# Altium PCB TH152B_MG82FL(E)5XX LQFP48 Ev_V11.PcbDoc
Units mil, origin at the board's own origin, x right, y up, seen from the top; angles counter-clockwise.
Board outline 2850 x 2110 mil, 2 copper layers (Top Layer, Bottom Layer); 49 components, 67 nets, 298 pads, 95 vias.
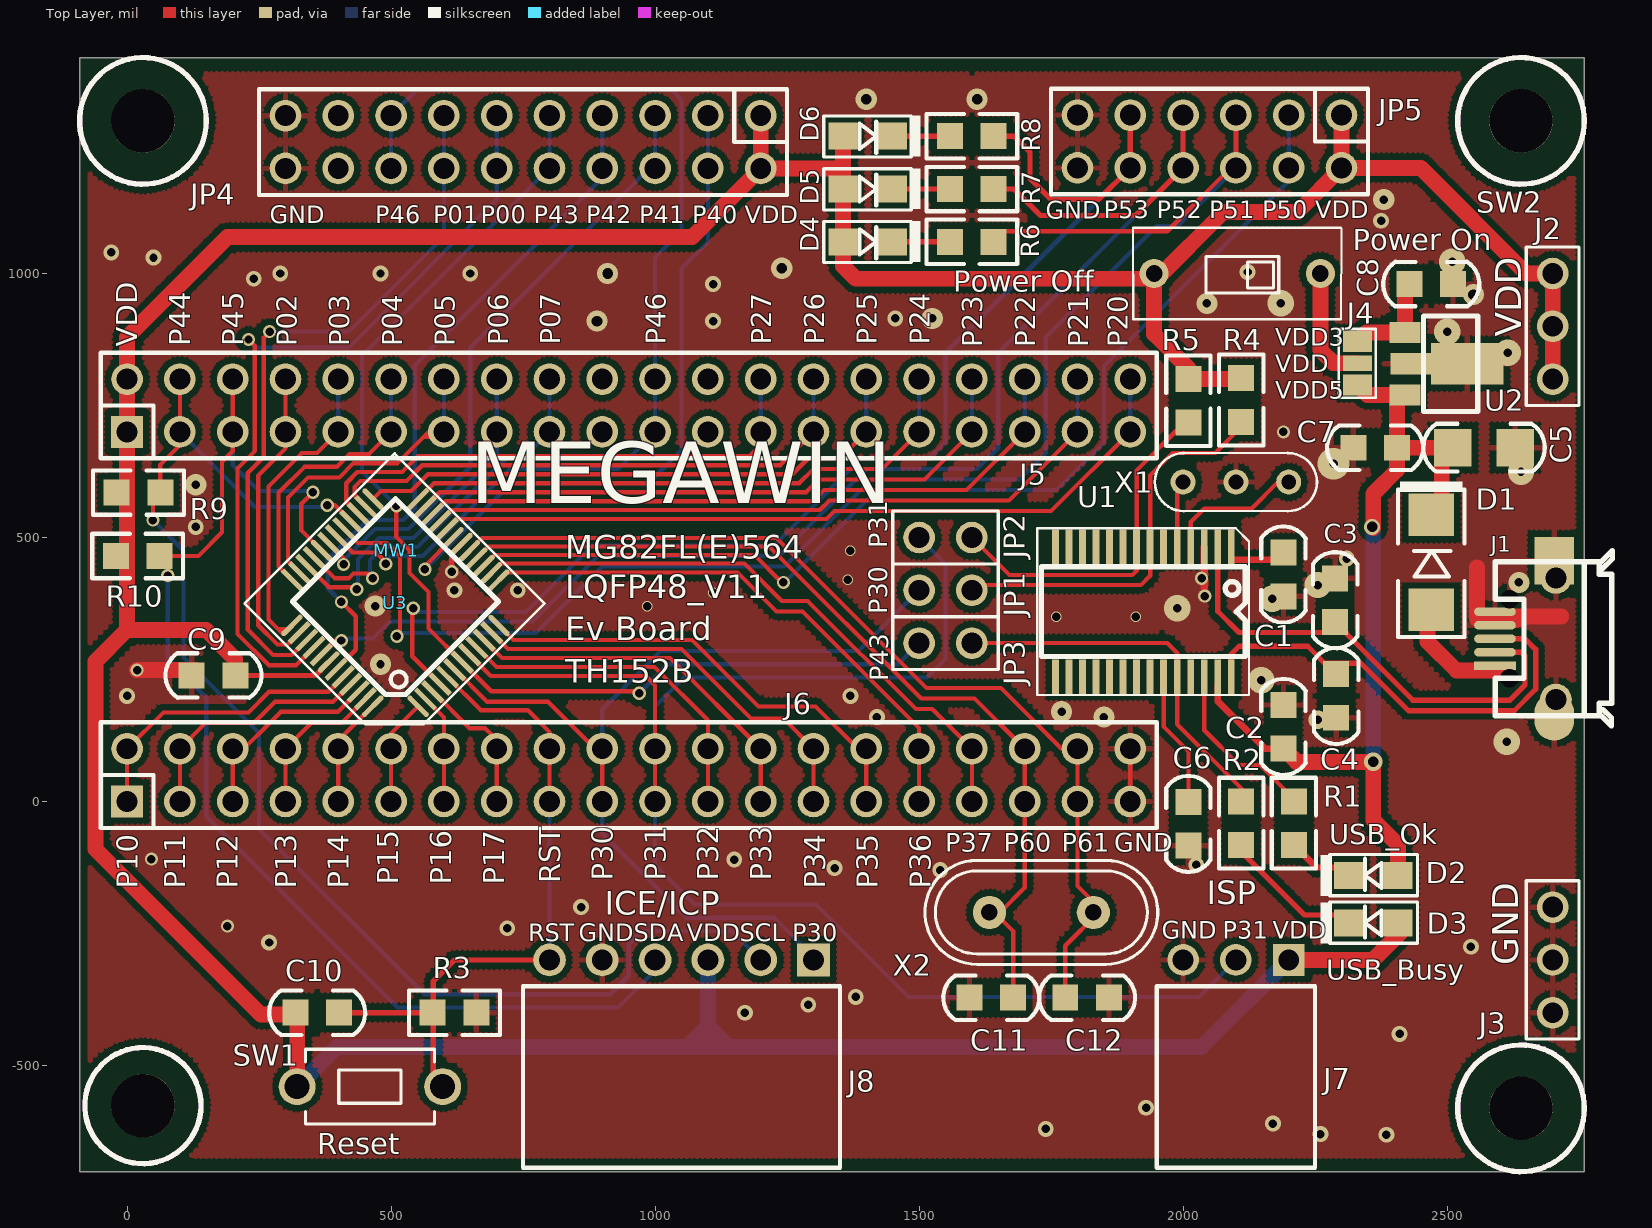
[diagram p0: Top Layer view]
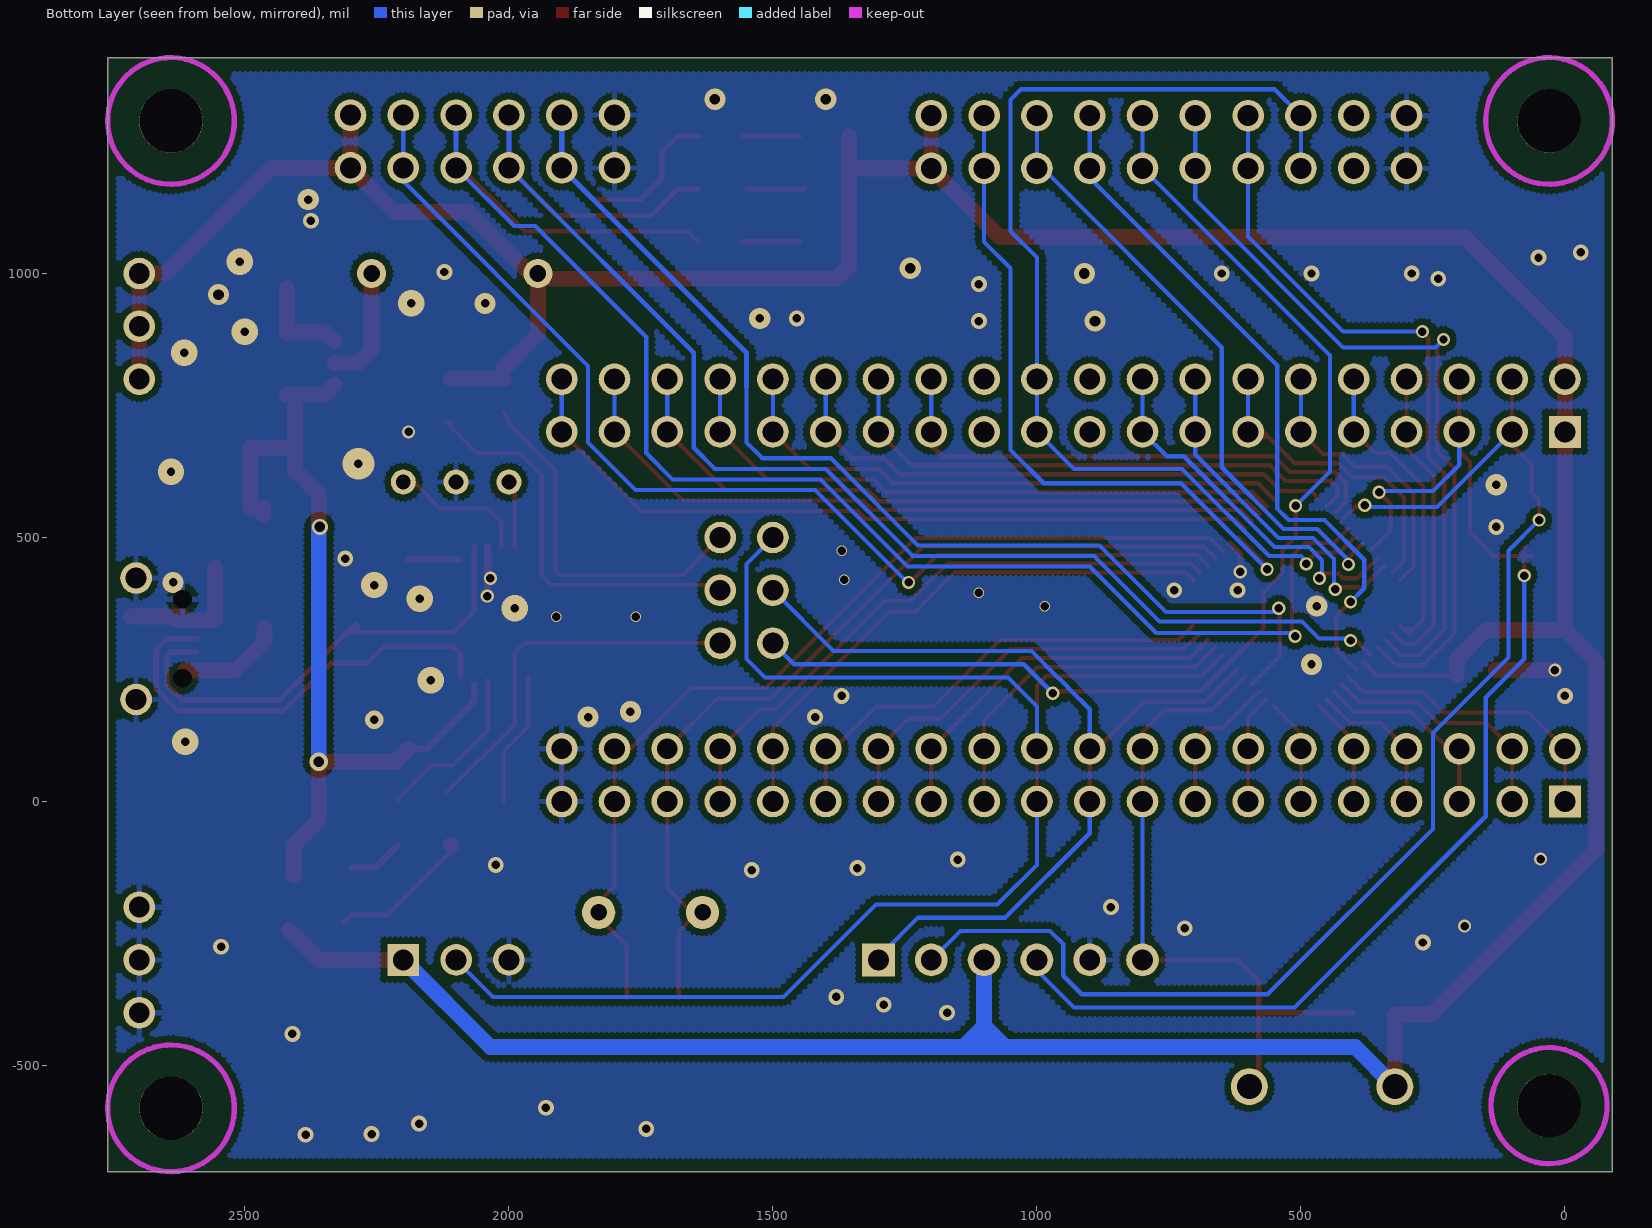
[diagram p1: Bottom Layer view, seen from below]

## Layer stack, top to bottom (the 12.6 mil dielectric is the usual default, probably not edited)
Top Layer: signal copper 1.4
Dielectric: dielectric 12.6, FR-4, Dk 4.8
Bottom Layer: signal copper 1.4

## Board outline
-90,-701 -90,1409 2760,1409 2760,-701

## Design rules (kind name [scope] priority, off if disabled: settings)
Clearance 12 [All] p1 off: gap=12
Clearance 10 [All] p2 off: gap=10
Clearance 6 [All] p3: gap=6
ComponentClearance [All] p1 off: gap=10 collisioncheckmode=3 verticalgap=10 showdistances=FALSE
HoleSize [All] p1: absolutevalues=TRUE maxlimit=500 minlimit=1 maxpercent=80.000 minpercent=20.000
MinimumSolderMaskSliver [All] p1 off: minsoldermaskwidth=10
PolygonConnect VIA [ISVIA] p1: connectstyle=Direct reliefconductorwidth=10 reliefentries=4 polygonreliefangle="90 Angle"
PolygonConnect [All] p2: connectstyle=Relief reliefconductorwidth=10 reliefentries=4 polygonreliefangle="90 Angle"
RoomDefinition "TH152B_MG82FL(E)5XX LQFP48 Ev_V10" [InComponentClass('TH152B_MG82FL(E)5XX LQFP48 Ev_V10')] p1: confinementstyle=ConfineIn formatcopy=TRUE lockcomponents=FALSE outline -685,-1335 3285,-1335 3285,1895 -685,1895
RoutingVias [All] p1: holewidth=16 width=25 viastyle="Through Hole" minholewidth=16 minwidth=24 maxholewidth=28 maxwidth=50
SilkToSilkClearance [All] p1 off: silktosilkclearance=10
SilkscreenOverComponentPads [All] p1 off: minsilkscreentomaskgap=10
SolderMaskExpansion [All] p1 off: expansion=4
Width [All] p1: maxlimit=200 minlimit=6 preferedwidth=10
23 further rules are at their usual default settings.

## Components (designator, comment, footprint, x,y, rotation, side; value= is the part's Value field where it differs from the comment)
C1 "4.7uF" 0805C 2190,430 r270 top
C2 "0.1uF" 0805C 2190,141.34 r270 top
C3 "15pF" 0805C 2288,381.34 r90 top
C4 "15pF" 0805C 2290,200 r270 top
C5 "4.7uF" 1206C 2570,670 r0 top
C6 "0.1uF" 0805C 2010,-42.34 r90 top
C7 "0.1uF" 0805C 2363.66,670 r180 top
C8 "4.7uF" 0805C 2470,980 r0 top
C9 "0.1uF" 0805C 163.66,238.85 r180 top
C10 "1u" 0805C 360,-400 r0 top
C11 "NC" 0805C 1636.81,-371.58 r180 top
C12 "NC" 0805C 1818.15,-371.58 r0 top
D1 "1N5817" D5817_SMD_1 2470,453 r270 top
D2 "Yellow" 0805D 2360,-140 r180 top
D3 "RED" 0805D 2360,-230 r180 top
D4 "Green" 0805D 1403.08,1060 r0 top
D5 "RED" 0805D 1403.08,1160 r0 top
D6 "Green" 0805D 1403.08,1260 r0 top
J1 "Micro USB母座" JACK_USB_SMD290X220P065 2590.71,308.28 r180 top
J2 "*" PS3P254 2700,800 r90 top
J3 "*" PS3P254 2700,-200 r270 top
J4 "*" JUMP3_SMD 2330,830 r90 top
J5 "*" PS20X2P254 0,700 r0 top locked
J6 "*" PS20X2P254 0,0 r0 top locked
J7 "*" PS3P254f_90 2200,-300 r180 top
J8 "*" PS6P254F_90 1300,-300 r180 top
JP1 "JUMPER2" PS2P254 1500,400 r0 top
JP2 "JUMPER2" PS2P254 1500,500 r0 top
JP3 "JUMPER2" PS2P254 1500,300 r0 top
JP4 "*" PS10X2P254 1200,1299 r180 top
JP5 "*" PS6X2P254 2300,1300 r180 top
MW1 "MW-A4" MEGAWIN_T 510,476 r0 top
R1 "1K" 0805R 2210,-41 r270 top
R2 "1K" 0805R 2110,-41 r270 top
R3 "47K" 0805R 620,-400 r180 top
R4 "4.7K" 0805R 2110,760.34 r270 top
R5 "4.7K" 0805R 2010,759 r270 top
R6 "1K" 0805R 1600,1060 r180 top
R7 "1K" 0805R 1600,1160 r180 top
R8 "1K" 0805R 1600,1260 r180 top
R9 "4.7K" 0805R 21.66,585 r180 top
R10 "4.7K" 0805R 20,465 r180 top
SW1 "SW TACT-SPST" SW_T_2P 460,-540 r0 top
SW2 "-" DIP2_SW 2260,1000 r180 top
U1 "MA101_TSSOP28" TSSOP28_170P065 1924.84,359.52 r180 top locked
U2 "AIC1734-33(SOT-89)" SOT89 2420,829.06 r270 top
U3 "MG82Fx564_LQFP48" LQFP48_7X7_050 551.24,180.26 r45 top locked (schematic designator U1)
X1 "6MHz" X3P 2200,605 r180 top
X2 "NC" X49U 1731.57,-210 r0 top

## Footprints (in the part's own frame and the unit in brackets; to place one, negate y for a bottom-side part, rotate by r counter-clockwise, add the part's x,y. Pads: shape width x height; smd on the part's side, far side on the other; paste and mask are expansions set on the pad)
0805C [mm]
  rect 1.25x1.25 smd: 1(-1.05,0) 2(1.05,0)
  silkscreen extent -2.31,-1.07 2.31,1.07
0805D [mm]
  rect 1.4x1.3 smd: 1(-1.192,0) 2(1.192,0)
  silkscreen extent -2.12,-1 2.53,0.98
0805R [mm]
  rect 1.25x1.25 smd: 1(-1.05,0) 2(1.05,0)
  silkscreen extent -2.18,-1.07 2.18,1.07
1206C [mm]
  rect 1.8x1.8 smd: 1(-1.5,0) 2(1.5,0)
  silkscreen extent -2.92,-1.15 2.92,1.16
D5817_SMD_1 [mil]
  rect 80x86.61 smd: 1(90,0) 2(-90,0)
  silkscreen extent -153,-63 142,63
DIP2_SW [mm]
  round 1.4 hole 0.8: 1(0,0) 2(8,0)
  silkscreen extent -1.02,-2.2 9.02,2.2
JACK_USB_SMD290X220P065 [mm]
  rect 1.9x1.8 on Mech2: 0(-2.85,-1.15) 0(-2.85,1.15)
  round 0.8 hole 0.9 unplated: 1(-0.7,1.9) 5(-0.7,-1.9)
  rect 2x0.4 smd: 1(0,1.3)
  oval 2x0.4 smd: 2(0,0.65) 3(0,0) 4(0,-0.65) 5(0,-1.3)
  round 1.524 hole 1: 5(-2.931,2.921) 5(-2.931,-2.921)
  oval 1.9x2.3 smd: 5(-2.85,3.75)
  rect 1.9x2.3 smd: 5(-2.85,-3.75)
  silkscreen extent -5.65,-4.25 -0.01,4.2
JUMP3_SMD [mil]
  rect 40x55 smd: 1(-41,0) 3(41,0)
  rect 30x55 smd: 2(0,0)
  silkscreen extent -65,-35 65,35
LQFP48_7X7_050 [mm]
  oval 0.254x1.35 smd: 1(0,0) 12(5.5,0) 25(5.513,8.585) 32(2.013,8.585)
  rect 0.254x1.35 smd: 2(0.5,0) 3(1,0) 4(1.5,0) 5(2,0) 6(2.5,0) 7(3,0) 8(3.5,0) 9(4,0) 10(4.5,0) 11(5,0) 26(5.013,8.585) 27(4.513,8.585) 28(4.013,8.585) 29(3.513,8.585) 30(3.013,8.585) 31(2.513,8.585) 33(1.513,8.585) 34(1.013,8.585) 35(0.513,8.585) 36(0.013,8.585)
  oval 1.35x0.254 smd: 13(7.036,1.549) 14(7.036,2.049) 15(7.036,2.549) 16(7.036,3.049) 17(7.036,3.549) 18(7.036,4.049) 19(6.921,4.549) 37(-1.536,7.049) 42(-1.536,4.549) 48(-1.536,1.549)
  rect 1.35x0.254 smd: 20(7.036,5.049) 21(7.036,5.549) 22(7.036,6.049) 23(7.036,6.549) 24(7.036,7.049) 38(-1.536,6.549) 39(-1.536,6.049) 40(-1.536,5.549) 41(-1.536,5.049) 43(-1.536,4.049) 44(-1.536,3.549) 45(-1.536,3.049) 46(-1.536,2.549) 47(-1.536,2.049)
  silkscreen extent -2.4,-0.8 7.8,9.4
MEGAWIN_T [mil]
PS2P254 [mil]
  round 60 hole 39.37: 1(0,0) 2(100,0)
  silkscreen extent -50,-50 150,50
PS3P254 [mil]
  round 60 hole 39.37: 1(0,0) 2(100,0) 3(200,0)
  silkscreen extent -50,-50 250,50
PS3P254f_90 [mil]
  rect 60x60 hole 39.37: 1(0,0)
  round 60 hole 39.37: 2(100,0) 3(200,0)
  silkscreen extent -50,50 250,394
PS6P254F_90 [mil]
  rect 62x62 hole 39.37: 1(0,0)
  round 62 hole 39.37: 2(100,0) 3(200,0) 4(300,0) 5(400,0) 6(500,0)
  silkscreen extent -50,50 550,394
PS6X2P254 [mil]
  round 60 hole 39.37: 1(0,0) 2(0,100) 3(100,0) 4(100,100) 5(200,0) 6(200,100) 7(300,0) 8(300,100) 9(400,0) 10(400,100) 11(500,0) 12(500,100)
  silkscreen extent -50,-50 550,150
PS10X2P254 [mil]
  round 60 hole 39.37: 1(0,0) 2(0,100) 3(100,0) 4(100,100) 5(200,0) 6(200,100) 7(300,0) 8(300,100) 9(400,0) 10(400,100) 11(500,0) 12(500,100) 13(600,0) 14(600,100) 15(700,0) 16(700,100) 17(800,0) 18(800,100) 19(900,0) 20(900,100)
  silkscreen extent -50,-50 950,150
PS20X2P254 [mil]
  rect 60x60 hole 39.37: 1(0,0)
  round 60 hole 39.37: 2(0,100) 3(100,0) 4(100,100) 5(200,0) 6(200,100) 7(300,0) 8(300,100) 9(400,0) 10(400,100) 11(500,0) 12(500,100) 13(600,0) 14(600,100) 15(700,0) 16(700,100) 17(800,0) 18(800,100) 19(900,0) 20(900,100) 21(1000,0) 22(1000,100) 23(1100,0) 24(1100,100) 25(1200,0) 26(1200,100) 27(1300,0) 28(1300,100) 29(1400,0) 30(1400,100) 31(1500,0) 32(1500,100) 33(1600,0) 34(1600,100) 35(1700,0) 36(1700,100) 37(1800,0) 38(1800,100) 39(1900,0) 40(1900,100)
  silkscreen extent -50,-50 1950,150
SOT89 [mm]
  rect 1.016x1.5 smd: 1(-1.5,0) 3(1.5,0)
  rect 2x3.5 smd: 2(0,3)
  rect 1.016x2.6 smd: 2(0,0.6)
  silkscreen extent -2.3,0.9 2.3,3.5
SW_T_2P [mil]
  round 70 hole 47.24: 1(-137.79,0) 2(137.79,0)
  silkscreen extent -122,-71 122,71
TSSOP28_170P065 [mil]
  rect 13x65 smd: 1(-166.34,-123) 2(-140.75,-123) 3(-115.16,-123) 4(-89.57,-123) 5(-63.98,-123) 6(-38.39,-123) 7(-12.79,-123) 8(12.8,-123) 9(38.39,-123) 10(63.98,-123) 11(89.57,-123) 12(115.16,-123) 13(140.75,-123) 14(166.34,-123) 15(166.34,123) 16(140.75,123) 17(115.16,123) 18(89.57,123) 19(63.98,123) 20(38.39,123) 21(12.8,123) 22(-12.79,123) 23(-38.39,123) 24(-63.98,123) 25(-89.57,123) 26(-115.16,123) 27(-140.75,123) 28(-166.34,123)
  silkscreen extent -200,-158 201,158
X3P [mm]
  round 1.2 hole 0.711: 1(0,0) 2(5.08,0) 3(2.54,0)
  silkscreen extent -1.36,-1.4 6.44,1.4
X49U [mm]
  round 1.6 hole 0.8: 1(-2.5,0) 2(2.5,0)
  silkscreen extent -5.6,-2.5 5.6,2.5

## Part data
C1 C5 C8: library part CAP
C2 C3 C4 C6 C7 C9: library part "CAP NP"
C10: library part C
C11 C12: library part "C NP"
D1: library part DIODE_ZD, "Schottky Diode"
D2 D3 D4 D5 D6: library part LED
J1: library part CON5, "Connector"
J2 J3 J4 J7: library part CON3
J5 J6: library part CON40A
J8: library part CON6
JP4: library part CON10X2
JP5: library part CON6X2
R1 R2 R4 R5 R6 R7 R8: library part R_Dup1
R3 R9 R10: library part R
SW2: library part SW-2
U2: library part AIC1734-33(SOT-89)_0
X1: library part CRYSTAL_RC
X2: library part CRYSTAL

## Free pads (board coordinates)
  round 120 hole 120 unplated: 0(30,-576) 0(30,1289) 0(2640,-581) 0(2640,1289)

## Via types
v1: diameter 30, hole 16, Top Layer to Bottom Layer, tented both sides, 35 vias
v2: diameter 25, hole 16, Top Layer to Bottom Layer, tented both sides, 25 vias
v3: diameter 50, hole 16, Top Layer to Bottom Layer, tented both sides, 10 vias
v4: diameter 40, hole 16, Top Layer to Bottom Layer, tented both sides, 9 vias
v5: diameter 20, hole 16, Top Layer to Bottom Layer, tented both sides, 6 vias
v6: diameter 40, hole 20, Top Layer to Bottom Layer, tented both sides, 6 vias
v7: diameter 35, hole 16, Top Layer to Bottom Layer, tented both sides, 1 vias
v8: diameter 30, hole 20, Top Layer to Bottom Layer, tented both sides, 1 vias
v9: diameter 35, hole 20, Top Layer to Bottom Layer, tented both sides, 1 vias
v10: diameter 60, hole 16, Top Layer to Bottom Layer, tented both sides, 1 vias

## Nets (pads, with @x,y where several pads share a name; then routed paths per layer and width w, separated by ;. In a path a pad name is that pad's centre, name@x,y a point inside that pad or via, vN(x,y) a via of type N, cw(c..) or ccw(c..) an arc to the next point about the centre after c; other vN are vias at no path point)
D+: C4.1 J1.3 U1.28 | length 853.6
  Top Layer w10: U1.28 2091.18,279.18 2106,294 2236,294 2268.16,261.84 2336.88,261.84 2426.72,172 2627.16,172 2667.71,212.55 2667.71,288.2 2647.64,308.28 J1.3
D-: C3.1 J1.2 U1.2 | length 933.5
  Top Layer w10: U1.2 2065.59,360.41 2106,320 C3.1@2288,320 ; C3.1@2288,335 C3.1@2288,320 ; C3.1@2296,331 C3.1@2307,320 ; C3.1@2309,320 C3.1@2307,320 ; J1.2 2641.14,282.69 2647.71,276.12 2647.71,220.84 2618.87,192 2435,192 C3.1@2307,320 ; C3.1@2288,320 C3.1@2307,320
GND_POWER: C1.2 C2.1 C3.2 C4.2 C5.2 C6.1 C7.2 C8.2 C9.2 C11.2 C12.2 J1.4 J1.5 J3.1 J3.2 J3.3 J6.39 J6.40 J7.3 J8.5 JP4.19 JP4.20 JP5.11 JP5.12 R3.1 U1.3 U2.2 U3.18 X1.3 | length 616
  Top Layer w8: J6.39 J6.40
  Top Layer w10: v2(615,435) 615,469.44 U3.18
  Top Layer w15: 2040,406 v2@2040,416 ; U1.3 v2@2040,416 ; v2@2041,415 v2@2040,416
  Top Layer w30: v2(19,248.85) C9.2@131,248.85 ; 2556.57,345.91 2556.57,443 ; 2560,343.32 2630,343.32 ; 2619.25,350.32 2716.34,350.32
  other v1: 2385,-631 2260,-630 1740,-620 2170,-610 1930,-580 2410,-440 1170,-400 1290,-385 1380,-370 2545,-275 269,-267 720,-240 860,-200 1540,-130 1340,-126 2025,-120 1150,-110 1420,160 0,200 1370,200 620,400 740,400 2310,460 130,520 1110,910 1455,915 1110,980 240,990 290,1000 480,1000 650,1000 2122.21,1002.83 50,1030 -30,1040 2375,1100
  other v2: 190,-236 46,-109 2041,389 2035,423 2190,700
  other v3: 2612.91,113 2148,230 1989,366 2169,384 2255,410 2640,624.9 2615,850 2500,890 2185,943.39 2510,1022
  other v4: 1850,160 1770,170 480,260 470,370 2636,415 130,600 1525,915 2045,943.39 2380,1140
  other v5: 1760,350 1910,350 985,370 1110,395 1365,420 1370,475
  other v6: 890,910 2550,960 910,1000 1240,1010 1400,1330 1610,1330
  other v7: 2255,155
  other v10: 2285,640
MA101_RX: JP2.2 R5.2 U1.8 | length 686.1
  Top Layer w8: JP2.2 1671.15,428.85 1903.85,428.85 1912.05,437.05 U1.8 1912.05,627.05 2001.33,716.33 2001.33,726.33 2010,735 R5.2@2010,737.66
MA101_TX: JP1.2 R4.2 U1.7 | length 755
  Top Layer w8: JP1.2@1610,410 1920,410 1937.64,427.64 1937.64,617.64 1980.12,660.12 2060.78,660.12 2110,709.34 R4.2 R4.2@2120,719
NetC1_1: C1.1 U1.1 | length 95.8
  Top Layer w13: U1.1@2094.2,458 C1.1@2190,458
NetC6_2: C6.2 U1.23 | length 306.3
  Top Layer w8: 1963.23,191.18 1963.23,141.77 ; U1.23 1963.23,141.77 ; C6.2 2010,95 1963.23,141.77
NetD1_1: D1.1 J1.1 | length 199.7
  Top Layer w30: D1.1@2463,330 2463,302.91 2517.91,248 J1.1@2612.91,248
NetD2_2: D2.2 R1.2 | length 105.7
  Top Layer w12: R1.2 2252.66,-125 D2.2@2298.08,-125
NetD3_2: D3.2 R2.2 | length 273
  Top Layer w10: R2.2 2110,-95 2230,-215 2298.08,-215 D3.2
  Top Layer w30: R2.2@2108.66,-82.34 R2.2
NetD4_2: D4.2 R6.2 | length 108.7
  Top Layer w10: D4.2 R6.2
NetD5_2: D5.2 R7.2 | length 108.7
  Top Layer w10: D5.2@1441.34,1160 D5.2 R7.2@1550,1160
NetD6_2: D6.2 R8.2 | length 108.7
  Top Layer w10: D6.2 R8.2
NetJ4_2: J4.2 SW2.1 | length 225.4
  Top Layer w30: SW2.1 2260,855 2285,830 J4.2
NetU1_4: U1.4 X1.1 | length 263.8
  Top Layer w8: U1.4 2014.41,529.41 2040,555 2130,555 2180,605 X1.1
NetU1_5: U1.5 X1.2 | length 127.1
  Top Layer w8: U1.5 1988.82,593.82 X1.2
P00: JP4.11 JP4.12 U3.40 | length 1511.1
  Top Layer w8: v2(230,875) 242,863 242,663.85 208.95,630.79 208.95,317.55 268.54,257.96 320.01,257.96 U3.40
  Bottom Layer w8: v2(230,875) 245,860 420,860 700,1140 JP4.12 JP4.11
P01: JP4.13 JP4.14 U3.39 | length 1472.1
  Top Layer w8: 259,864 259,750 ; v2(270,890) 259,879 259,750 ; U3.39 311.85,277.64 276.69,277.64 228.63,325.71 228.63,622.48 259,652.85 259,750
  Bottom Layer w8: v2(270,890) 420,890 600,1070 JP4.14 JP4.13
P02: J5.7 J5.8 U3.38 | length 564.8
  Top Layer w8: J5.7 300,668.85 248.32,617.16 248.32,333.86 284.85,297.33 303.7,297.33 U3.38 ; J5.7@300,725 J5.8
P03: J5.9 J5.10 U3.37 | length 607.6
  Top Layer w8: U3.37@303.7,326.85 285.71,326.85 ; U3.37 295.54,317.01 285.71,326.85 ; J5.9 359.84,659.84 330.99,659.84 268,596.85 268,344.56 285.71,326.85
  Bottom Layer w8: J5.9 J5.10
P04: J5.11 J5.12 U3.36 | length 536.6
  Top Layer w8: U3.36 287,445.21 287,584.85 336,633.85 397,633.85 421,657.85 457.85,657.85 J5.11
  Bottom Layer w8: J5.11 J5.12
P05: J5.13 J5.14 U3.35 | length 638.2
  Top Layer w8: U3.35 305,455.04 305,575.85 343,613.85 402,613.85 429,640.85 512,640.85 571.15,700 J5.13 ; 563.44,690.85 J5.13@604,690.85
  Bottom Layer w8: J5.13 J5.14
P06: J5.15 J5.16 U3.34 | length 663.2
  Top Layer w8: U3.34 381.88,406 431,406 v2(435,402)
  Bottom Layer w8: v2@437.23,397.23 437.23,459.23 477,499 542.21,499 700,656.79 J5.15 J5.16
P07: J5.17 J5.18 U3.33 | length 708.6
  Top Layer w8: U3.33 392.72,423 420,423 429,432 456,432 v2(465,423)
  Bottom Layer w8: v2@460,423 460,457 484.85,481.85 550,481.85 722,653.85 753.85,653.85 J5.17 J5.18
P10: J6.1 J6.2 U3.44 | length 566.1
  Top Layer w8: J6.1 J6.2 68.85,168.85 230,168.85 269,207.85 381.25,207.85 U3.44
P11: J6.3 J6.4 U3.45 | length 474.3
  Top Layer w8: J6.3 J6.4 148.85,148.85 240,148.85 280,188.85 390.09,188.85 U3.45
P12: J6.5 J6.6 U3.46 | length 370.1
  Top Layer w8: J6.5 200,78.85 291,169.85 398.93,169.85 U3.46
P13: J6.7 J6.8 U3.47 | length 290.6
  Top Layer w8: J6.7 J6.8 348.85,148.85 405.77,148.85 U3.47
P14: J6.9 J6.10 U3.48 | length 192.4
  Top Layer w8: J6.9 J6.10 ; J6.10@400,115.24 U3.48
P15: J6.11 J6.12 U3.1 | length 201.5
  Top Layer w8: J6.11 J6.12 500,129.01 U3.1
P16: J6.13 J6.14 U3.2 | length 208.6
  Top Layer w8: U3.2 600,159.34 J6.14 J6.13
P17: J6.15 J6.16 U3.3 | length 246
  Top Layer w8: U3.3 648.33,138.85 678,138.85 J6.16@691,125.85 ; J6.15 J6.16
P20: J5.39 J5.40 U3.20 | length 1469.4
  Top Layer w8: U3.20 624.73,534.85 1324.85,534.85 1340,550 1750,550 J5.39
  Bottom Layer w8: J5.39 J5.40
P21: J5.37 J5.38 U3.21 | length 1377.5
  Top Layer w8: U3.21 613.9,551.85 1311.85,551.85 1330,570 1670,570 J5.37
  Bottom Layer w8: J5.37 J5.38
P22: J5.35 J5.36 U3.22 | length 1285.7
  Top Layer w8: U3.22 603.06,568.85 1298.85,568.85 1320,590 1590,590 J5.35
  Bottom Layer w8: J5.35 J5.36
P23: J5.33 J5.34 U3.23 | length 1193.8
  Top Layer w8: U3.23 592.22,585.85 1285.85,585.85 1310,610 1510,610 J5.33
  Bottom Layer w8: J5.33 J5.34
P24: J5.31 J5.32 U3.24 | length 1102
  Top Layer w8: U3.24 581.38,602.85 1272.85,602.85 1300,630 1430,630 J5.31
  Bottom Layer w8: J5.31 J5.32
P25: J5.29 J5.30 U3.25 | length 1087
  Top Layer w8: U3.25 480.86,587.85 538.15,587.85 570.15,619.85 1259.85,619.85 1290,650 1350,650 J5.29
  Bottom Layer w8: J5.29 J5.30
P26: J5.27 J5.28 U3.26 | length 1057.8
  Top Layer w8: U3.26 431,579.59 431,595.85 442,606.85 529,606.85 559,636.85 1236.85,636.85 J5.27
  Bottom Layer w8: J5.27 J5.28
P27: J5.25 J5.26 U3.27 | length 1002.2
  Top Layer w8: U3.27 415,567.75 415,602.85 436,623.85 521,623.85 551,653.85 1022,653.85 ; 1042,653.85 1022,653.85 ; J5.25@1200,674.7 1179.15,653.85 1022,653.85
  Bottom Layer w8: J5.25 J5.26
P30_RXD: J6.19 J6.20 J8.1 JP1.1 U3.6 | length 1783.7
  Top Layer w8: U3.6 681.84,188.85 797.15,188.85 900,86 J6.19
  Bottom Layer w8: J6.19 900,-60 1060,-220 1225,-220 1290,-285 1290,-310 J8.1@1300,-320 ; J6.20 900,174.7 941.5,216.2 941.5,216.81 958.19,233.5 958.8,233.5 1010.3,285 1385,285 JP1.1
P31_TXD: J6.21 J6.22 J7.2 JP2.1 U3.8 | length 2855.8
  Top Layer w8: U3.8 688.67,237.7 982.3,237.7 1000,220 J6.22 ; J6.21 J6.22@1000,90
  Bottom Layer w8: J6.21 1000,-120 1075,-195 1305,-195 1480,-370 2030,-370 J7.2 ; J6.22 1000,180 1055,235 1515,235 1550,270 1550,450 JP2.1
P32: J6.23 J6.24 U3.9 | length 648.3
  Top Layer w8: U3.9 699.51,254.7 999.15,254.7 1100,153.85 J6.24 J6.23
P33: J6.25 J6.26 U3.10 | length 708.6
  Top Layer w8: U3.10 710.35,271.7 1028.3,271.7 J6.26 J6.25
P34: J6.27 J6.28 U3.11 | length 800.5
  Top Layer w8: U3.11 721.19,288.7 1050,288.7 1181.8,156.9 1243.1,156.9 J6.28 J6.27
P35: J6.29 J6.30 U3.12 | length 889.8
  Top Layer w8: U3.12@720.29,317.44 U3.12 732.03,305.7 1070,305.7 1195.7,180 1304,180 1384,100 J6.30 ; J6.29 J6.30@1400,75
P36: J6.31 J6.32 U3.13 | length 1063.3
  Top Layer w8: U3.13 718.76,434 1156,434 1230,360 1279,360 1500,139 J6.32 J6.31
P37: J6.33 J6.34 U3.14 | length 1162.7
  Top Layer w8: U3.14 707.92,451 1169,451 1240,380 1289,380 1494,175 1525,175 J6.34 J6.33
P40: JP4.3 JP4.4 U3.19 | length 1345.8
  Top Layer w8: v2@563,439 563,445.28 U3.19 597.57,479.85
  Bottom Layer w8: v2@563,439 v2(564,440) 726.85,602.85 987,602.85 1050,665.85 1050,1010 1100,1060 JP4.4 JP4.3
P41: JP4.5 JP4.6 U3.31 | length 1191.6
  Top Layer w8: U3.31 410,461.4 v2(410,449) v2@410,445
  Bottom Layer w8: v2@410,445 v2(410,449) 410,457 469,516 533,516 650,633 650,860 1000,1210 JP4.5
P42: JP4.7 JP4.8 U3.43 | length 1341.4
  Top Layer w8: U3.43 433,287.44 433,351 v2(406,378)
  Bottom Layer w8: v2(406,378) 380,404 380,458 455,533 523,533 545,555 545,826.17 900,1181.17 JP4.8 JP4.7
P43: JP3.1 JP4.9 JP4.10 U3.7 | length 2200.7
  Top Layer w8: v2(510,560) 510,501 535,476 535,433 571,397 571,327.53 U3.7 689.68,208.85 v2@970,208.85
  Bottom Layer w8: v2(510,560) 445,625 445,845 800,1200 JP4.9 ; v2(970,205) 1025,260 1460,260 JP3.1 JP3.1@1491.15,308.85
P44: J5.3 J5.4 J8.2 R9.1 U3.28 | length 2560.1
  Top Layer w8: v2(49,533) 49,571 R9.1 63,638 100,675 J5.3 J5.4 ; v2(379,561) 393.92,561 U3.28
  Bottom Layer w8: v2(49,533) 107,475 107,272.72 250,129.72 250,-52 563,-365 915,-365 950,-330 950,-270 975,-245 1145,-245 J8.2 J8.2@1200,-320 ; J5.3 242,558 376.15,558 v2@379,560.85
P45: J5.5 J5.6 J8.4 R10.1 U3.32 | length 2373.8
  Top Layer w8: R10.1 R10.1@77,465 ; v2(77,427.85) R10.1@77,465 ; R10.1@77,480.66 R10.1@77,465 ; J5.6 J5.5 200,663.49 180,643.49 180,510 135,465 R10.1@77,465 ; v2(352,585.85) 330,563.85 330,513.56 U3.32
  Bottom Layer w8: v2(77,427.85) 77,270 150,197 150,-28 512,-390 930,-390 J8.4@1000,-320 ; J5.5 200,637.85 250,587.85 v2@352,587.85
P46: J5.21 J5.22 JP4.15 JP4.16 U3.30 | length 2038.1
  Top Layer w8: U3.30 427.39,471.85 472,471.85 v2@489,454.85
  Bottom Layer w8: v2(490,450) 490,455 500,465 560,465 725,630 930,630 J5.21 J5.22@1000,780 ; JP4.16 JP4.15 550,1349 1030,1349 1050,1329 1050,1080 1000,1030 J5.22
P50: JP5.3 JP5.4 U3.15 | length 2082.4
  Top Layer w8: U3.15 696.08,467 1188,467 v2@1240,415
  Bottom Layer w8: v2@1240,420 v2@1245,415 ; v2(1243,415) v2@1245,415 ; JP5.3 JP5.4 2200,1175 1850,825 1850,680 1760,590 1420,590 v2@1245,415
P51: JP5.5 JP5.6 R6.1 U3.29 | length 3070.5
  Top Layer w8: U3.29 437.23,489.85 492,489.85 517,464.85 v2@517,319 ; R6.1 1661.34,1080 1970,1080 JP5.6@2100,1210
  Top Layer w10: JP5.6@2100,1210 JP5.5
  Bottom Layer w8: v2(511,313) 517,319 773.89,319 899.89,445 1245,445 1410,610 1690,610 1740,660 1740,880 1950,1090 1990,1090 JP5.6 2100,1235
  Bottom Layer w10: 2100,1235 JP5.5
P52: JP5.7 JP5.8 R7.1 U3.41 | length 2736
  Top Layer w8: U3.41 v2@398.88,309
  Top Layer w10: R7.1 1680,1160 1730,1110 1910,1110 JP5.8 JP5.7
  Bottom Layer w8: v2@398.88,309 466,309 498,341 767.6,341 891.6,465 1235,465 1400,630 1610,630 1650,670 1650,850 JP5.8
  Bottom Layer w10: JP5.8 JP5.7
  other v2: 406,305
P53: JP5.9 JP5.10 R8.1 U3.4 | length 2539.3
  Top Layer w8: v2@540,366 540,275.01 U3.4
  Top Layer w10: R8.1 1680,1260 1710,1230 1710,1180 1750,1140 1840,1140 JP5.10 JP5.9
  Bottom Layer w8: v2@540,366 v2(542,366) 549,359 755.6,359 881.6,485 1225,485 1390,650 1520,650 1550,680 1550,785
  Bottom Layer w10: 1550,785 1550,850 JP5.10 JP5.9
P60: C11.1 J6.35 J6.36 U3.16 X2.1 | length 1711
  Top Layer w8: U3.16 684.24,483 1216,483 1504,195 1605,195 J6.36 J6.35 1700,-163.15 X2.1@1653.15,-210 ; X2.1@1643.15,-210 1678.15,-245 C11.1
P61: C12.1 J6.37 J6.38 U3.17 X2.2 | length 1979
  Top Layer w8: U3.17 672.4,499 1230,499 1514,215 1655,215 1770,100 J6.38 J6.37 ; C12.1 1776.81,-273.19 X2.2@1840,-210 ; 1800,-126.58 J6.37 ; X2.2@1845,-215 1850,-210 1800,-160 J6.37
RST: C10.2 J6.17 J6.18 J8.6 R3.2 SW1.2 U3.5 | length 1301.9
  Top Layer w8: U3.5 670,172.85 759,172.85 800,131.85 J6.18 J6.17 ; J8.6@790,-300 J8.6
  Top Layer w10: C10.2 R3.2 ; SW1.2@580,-540 580,-340 620,-300 J8.6@790,-300
  Bottom Layer w8: J8.6@800,-320 J8.6 J6.17
USB_BUSY: JP3.2 R2.1 U1.24 | length 1118.3
  Top Layer w8: JP3.2 1930,300 ; 1655,300 1930,300 ; 2080,55 1988.82,146.18 ; R2.1@2118,17 1988.82,146.18 ; 1930,300 1970,300 1988.82,281.18 U1.24 1988.82,146.18
USB_OK: R1.1 U1.26 | length 408.4
  Top Layer w8: U1.26@2040,230 2040,135 ; 2100,75 2040,135 ; R1.1 2210,5 2146,69 2106,69 2040,135
VDD: C9.1 C10.1 D3.1 D4.1 D5.1 D6.1 J2.1 J2.2 J2.3 J5.1 J5.2 J7.1 J8.3 JP4.1 JP4.2 JP5.1 JP5.2 R4.1 R5.1 R9.2 R10.2 SW1.1 SW2.2 U3.42 | length 8514.6
  Top Layer w10: C9.1@210.34,234.7 214.49,238.85 356.57,238.85 U3.42
  Top Layer w30: C9.1 205,269.51 149.51,325 0,325 ; SW1.1 322.21,-403.54 253.54,-403.54 -60,-90 -60,265 0,325 ; JP4.1 JP4.2 ; 1355.16,1199 JP4.2 ; D6.1 D5.1 D4.1 1356.16,1013.84 1380,990 SW2.2@1945.04,990 ; R5.1 R4.1@2110,800.34 ; R5.1@2010,820.34 1945.04,885.3 SW2.2@1945.04,990 ; J7.1 2360,-300 D3.1@2416.92,-243.08 ; JP5.1 JP5.2 ; J2.1 J2.2 J2.3 2650,1000 2450,1200 JP5.2 ; 0,325 J5.1 J5.2 0,879 190,1069 1070,1069 JP4.2 ; SW2.2@1945.04,990 1950,990 2076.61,1116.61 2216.61,1116.61 JP5.2
  Bottom Layer w30: SW1.1 397.21,-465 1060,-465 ; J8.3@1100,-320 1100,-425 ; J7.1 2035,-465 1140,-465 ; 1060,-465 1100,-465 ; 1060,-465 1100,-425 ; 1100,-465 1140,-465 ; 1100,-465 1100,-425 ; 1100,-425 1140,-465
VDD3: C8.1 J4.3 U2.1 | length 180.3
  Top Layer w30: J4.3 2347.11,888.11 U2.1 C8.1@2420,971.34
VDD5: C2.2 C5.1 C7.1 D1.2 D2.1 J4.1 U1.27 U2.3 | length 1613
  Top Layer w13: U1.27@2065.59,220 2065.59,190 2155.59,100 C2.2
  Top Layer w30: C2.2 2215,75 v9(2360,75) 2360,-35 2406.92,-81.92 D2.1 ; J4.1 2349,770 U2.3@2405,770 ; v8@2360,518 2360,583 2405,628 C7.1 U2.3@2405,770 ; C7.1@2420,670 C5.1@2490,670 ; U2.3 U2.3@2405,770 ; D1.2@2466,543 D1.2@2466,558 ; D1.2@2490,555 C5.1@2490,663
  Bottom Layer w30: v9(2360,75) v8@2360,520
  other v8: 2358,520
pads on no net: J1.0 J5.19 J5.20 J5.23 J5.24 JP4.17 JP4.18 U1.6 U1.9 U1.10 U1.11 U1.12 U1.13 U1.14 U1.15 U1.16 U1.17 U1.18 U1.19 U1.20 U1.21 U1.22 U1.25

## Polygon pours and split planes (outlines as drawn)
GND_POWER on Bottom Layer "Bottom Layer-No Net" (hatched 90Degree grid 10 track 10, remove dead copper, pour order 1000): -70,-672 2740,-672 2740,1379 -70,1379
GND_POWER on Top Layer "Bottom Layer-No Net" (hatched 90Degree grid 10 track 10, remove dead copper, pour order 1000): -70,-672 2740,-672 2740,1379 -70,1379

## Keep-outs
Keep-Out Layer:
  circle w10: c2640,-581 r120
  circle w10: c30,1289 r120
  circle w10: c30,-576 r110
  circle w10: c2640,1289 r120

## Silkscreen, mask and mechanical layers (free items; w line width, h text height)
Top Overlay:
  circle w10: c2640,-581 r120
  circle w10: c30,1289 r120
  circle w10: c30,-576 r110
  circle w10: c2640,1289 r120
  text "P53" at 1850,1105 h33
  text "P52" at 1950,1105 h33
  text "P51" at 2050,1105 h33
  text "P50" at 2150,1105 h33
  text "VDD" at 2250,1105 h33
  text "GND" at 1740,1104 h33
  text "GND" at 270,1095 h33
  text "P46" at 470,1095 h33
  text "P01" at 580,1095 h33
  text "P00" at 670,1095 h33
  text "P43" at 770,1095 h33
  text "P42" at 870,1095 h33
  text "P41" at 970,1095 h33
  text "P40" at 1070,1095 h33
  text "VDD" at 1170,1095 h33
  text "Power On" at 2321,1044 h40
  text "Power Off" at 1565,965 h40
  text "VDD" at 2640,880 h50 r90
  text "P07" at 820,865 h38 r90
  text "P46" at 1020,865 h38 r90
  text "P27" at 1220,865 h38 r90
  text "P26" at 1320,865 h38 r90
  text "P25" at 1420,865 h38 r90
  text "P24" at 1520,865 h38 r90
  text "P06" at 722,864 h38 r90
  text "VDD3" at 2174.25,863 h33
  text "P44" at 120,862 h40 r90
  text "P45" at 220,862 h40 r90
  text "P02" at 321,862 h38 r90
  text "P03" at 421,862 h38 r90
  text "P04" at 521,862 h38 r90
  text "P05" at 621,862 h38 r90
  text "VDD" at 19,861 h40 r90
  text "P23" at 1620,860 h38 r90
  text "P22" at 1720,860 h38 r90
  text "P21" at 1820,860 h38 r90
  text "P20" at 1895,860 h38 r90
  text "VDD" at 2174.25,813 h33
  text "VDD5" at 2174.25,763 h33
  text "P31" at 1440,480 h35 r90
  text "MG82FL(E)564" at 830,460 h45
  text "LQFP48_V11" at 830,385 h45
  text "P30" at 1440,355 h35 r90
  text "Ev Board" at 830,305.7 h45
  text "P43" at 1441.31,227.69 h35 r90
  text "TH152B" at 830,225 h45
  text "USB_Ok" at 2277,-81 h38
  text "P37" at 1550,-95 h35
  text "P60" at 1660,-95 h35
  text "P61" at 1770,-95 h35.43
  text "GND" at 1870,-95 h35.43
  text "P30" at 920,-150 h40 r90
  text "P31" at 1020,-150 h40 r90
  text "P32" at 1120,-150 h40 r90
  text "P33" at 1220,-150 h40 r90
  text "RST" at 820,-155 h40 r90
  text "P15" at 513.95,-158.05 h40 r90
  text "P16" at 613.95,-158.05 h40 r90
  text "P17" at 713.95,-158.05 h40 r90
  text "P10" at 20,-165 h40 r90
  text "P11" at 110,-165 h40 r90
  text "P12" at 210,-165 h40 r90
  text "P13" at 320,-165 h40 r90
  text "P14" at 420,-165 h40 r90
  text "P34" at 1322,-165 h40 r90
  text "P35" at 1422,-165 h40 r90
  text "P36" at 1522,-165 h40 r90
  text "ISP" at 2045,-195 h45
  text "ICE/ICP" at 905,-214.47 h45
  text "GND" at 1960,-260 h33
  text "P31" at 2075,-260 h33
  text "VDD" at 2170,-260 h33
  text "RST" at 760,-264.47 h33
  text "GND" at 855,-264.47 h33
  text "SDA" at 960,-264.47 h33
  text "VDD" at 1060,-264.47 h33
  text "SCL" at 1160,-264.47 h33
  text "P30" at 1260,-264.47 h33
  text "GND" at 2635,-310 h50 r90
  text "USB_Busy" at 2271,-338 h38
  text "Reset" at 360,-668 h40
Mechanical 1:
  the board outline again, w13

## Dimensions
-90,1409 to -90,-701 on Top Overlay
-90,-701 to 2760,-701 on Top Overlay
